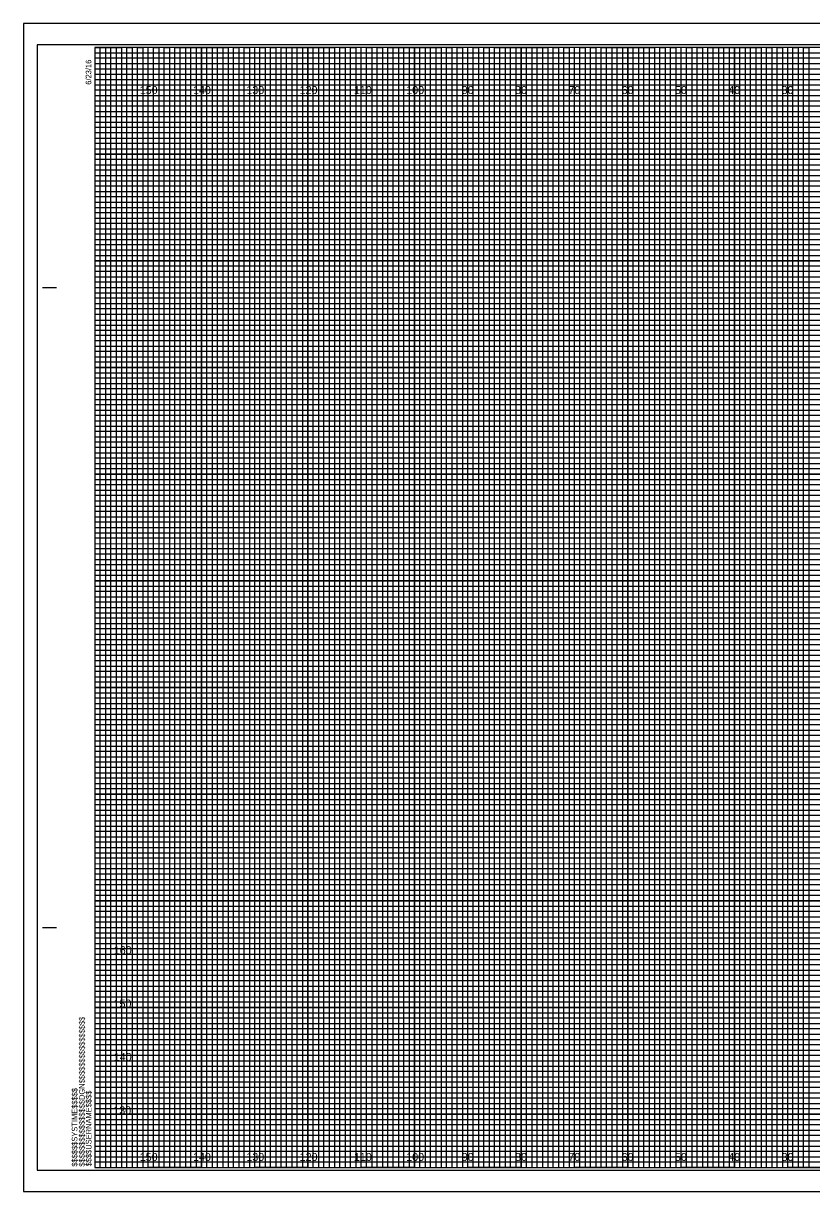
# Model space of a CAD drawing. Extents: x -13 to 323, y -5 to 874.
# Drawn here: x -13.4 to 134.5, y 655.5 to 874.5 of the extents above; entities that cross this region are included whole.
import ezdxf

# ---------------------------------------------------------------- set-up
doc = ezdxf.new("R2010")
doc.units = 0
for name, color, linetype in [('Exist Cross Section Cell', 7, 'Continuous'), ('Exist XS Center Line Elevation Label', 7, 'Continuous'), ('Exist XS Ground Line', 7, 'Continuous'), ('Prop CMT Pvmt Course 1', 7, 'Continuous'), ('Prop CMT Pvmt Course 3', 7, 'Continuous'), ('Prop CMT Pvmt Surface', 7, 'Continuous'), ('Prop CMT Pvmt Surface Shoulder', 7, 'Continuous'), ('Prop CMT Shld Paved Course 1', 7, 'Continuous'), ('Prop CMT Shld Paved Course 2', 7, 'Continuous'), ('Prop CMT Shld Paved Course 3', 7, 'Continuous'), ('Prop CMT Subgrade Earthwork', 7, 'Continuous')]:
    doc.layers.add(name, color=color, linetype=linetype)

msp = doc.modelspace()

# ---------------------------------------------------------------- linework, layer by layer
at = {"layer": 'Exist XS Center Line Elevation Label'}
for points in [[(0, 870), (5, 870), (5, 660), (15, 660), (15, 870), (25, 870), (25, 660), (35, 660), (35, 870), (45, 870), (45, 660), (55, 660), (55, 870), (65, 870), (65, 660), (75, 660), (75, 870), (85, 870), (85, 660), (95, 660), (95, 870), (105, 870), (105, 660), (115, 660), (115, 870), (125, 870), (125, 660), (135, 660)], [(0, 865), (275, 865)], [(0, 845), (320, 845), (320, 855), (0, 855)], [(0, 825), (320, 825), (320, 835), (0, 835)], [(0, 805), (320, 805), (320, 815), (0, 815)], [(0, 785), (320, 785), (320, 795), (0, 795)], [(0, 765), (320, 765), (320, 775), (0, 775)], [(0, 745), (320, 745), (320, 755), (0, 755)], [(0, 725), (320, 725), (320, 735), (0, 735)], [(0, 705), (320, 705), (320, 715), (0, 715)], [(0, 685), (320, 685), (320, 695), (0, 695)], [(0, 665), (320, 665), (320, 675), (0, 675)]]:
    msp.add_lwpolyline(points, dxfattribs=at)
at = {"layer": 'Exist XS Ground Line'}
for p, q in [((10, 870), (0, 870)), ((10, 660), (10, 870)), ((30, 870), (20, 870)), ((20, 870), (20, 660)), ((30, 660), (30, 870)), ((50, 870), (40, 870)), ((40, 870), (40, 660)), ((50, 660), (50, 870)), ((70, 870), (60, 870)), ((60, 870), (60, 660)), ((70, 660), (70, 870)), ((90, 870), (80, 870)), ((80, 870), (80, 660)), ((90, 660), (90, 870)), ((110, 870), (100, 870)), ((100, 870), (100, 660)), ((110, 660), (110, 870)), ((130, 870), (120, 870)), ((120, 870), (120, 660)), ((130, 660), (130, 870)), ((20, 660), (10, 660)), ((40, 660), (30, 660)), ((60, 660), (50, 660)), ((80, 660), (70, 660)), ((100, 660), (90, 660)), ((120, 660), (110, 660)), ((140, 660), (130, 660))]:
    msp.add_line(p, q, dxfattribs=at)
for points in [[(0, 860), (320, 860), (320, 850), (0, 850)], [(0, 840), (320, 840), (320, 830), (0, 830)], [(0, 820), (320, 820), (320, 810), (0, 810)], [(0, 800), (320, 800), (320, 790), (0, 790)], [(0, 780), (320, 780), (320, 770), (0, 770)], [(0, 760), (320, 760), (320, 750), (0, 750)], [(0, 740), (320, 740), (320, 730), (0, 730)], [(0, 720), (320, 720), (320, 710), (0, 710)], [(0, 700), (320, 700), (320, 690), (0, 690)], [(0, 680), (320, 680), (320, 670), (0, 670)]]:
    msp.add_lwpolyline(points, dxfattribs=at)
at = {"layer": 'Prop CMT Pvmt Course 3'}
msp.add_lwpolyline([(-13.4, 655.5), (323.3, 655.5), (323.3, 874.5), (-13.4, 874.5)], close=True, dxfattribs=at)
at = {"layer": 'Prop CMT Pvmt Surface'}
for p, q in [((10, 660), (10, 870)), ((20, 660), (20, 870)), ((30, 660), (30, 870)), ((40, 660), (40, 870)), ((50, 660), (50, 870)), ((60, 660), (60, 870)), ((70, 660), (70, 870)), ((80, 660), (80, 870)), ((90, 660), (90, 870)), ((100, 660), (100, 870)), ((110, 660), (110, 870)), ((120, 660), (120, 870)), ((130, 660), (130, 870)), ((0, 860), (320, 860)), ((0, 850), (320, 850)), ((0, 840), (320, 840)), ((0, 830), (320, 830)), ((0, 820), (320, 820)), ((0, 810), (320, 810)), ((0, 800), (320, 800)), ((0, 790), (320, 790)), ((0, 780), (320, 780)), ((0, 770), (320, 770)), ((0, 760), (320, 760)), ((0, 750), (320, 750)), ((0, 740), (320, 740)), ((0, 730), (320, 730)), ((0, 720), (320, 720)), ((0, 710), (320, 710)), ((0, 700), (320, 700)), ((0, 690), (320, 690)), ((0, 680), (320, 680)), ((0, 670), (320, 670))]:
    msp.add_line(p, q, dxfattribs=at)
at = {"layer": 'Prop CMT Pvmt Surface Shoulder'}
for p, q in [((323.3, 874.5), (-13.4, 874.5)), ((-13.4, 874.5), (-13.4, 655.5)), ((-13.4, 655.5), (323.3, 655.5))]:
    msp.add_line(p, q, dxfattribs=at)
at = {"layer": 'Prop CMT Shld Paved Course 1'}
for p, q in [((0, 869), (260, 869)), ((260, 867.98), (0, 867.98)), ((0, 867.98), (0, 867)), ((0, 867), (260, 867)), ((260, 865.89), (0, 865.89)), ((0, 865.89), (0, 864)), ((0, 864), (320, 864))]:
    msp.add_line(p, q, dxfattribs=at)
for points in [[(0, 863), (270, 863), (320, 863), (320, 862), (0, 862)], [(0, 861), (320, 861), (320, 859), (0, 859)], [(0, 858), (320, 858), (320, 857), (0, 856.98)], [(0, 856), (320, 856), (320, 854), (0, 854)], [(0, 853), (320, 853), (320, 852), (0, 852)], [(0, 851), (320, 851), (320, 849), (0, 849)], [(0, 848), (320, 848), (320, 847), (0, 847)], [(0, 846), (320, 846), (320, 844), (0, 844)], [(0, 843), (320, 843), (320, 842), (0, 842)], [(0, 841), (320, 841), (320, 839), (0, 839)], [(0, 838), (320, 838), (320, 837), (0, 837)], [(0, 836), (320, 836), (320, 833.95), (320, 833), (320, 832), (0, 832)], [(0, 834), (320, 834), (320, 833), (0, 833)], [(0, 831), (320, 831), (320, 829), (0, 829.03)], [(0, 829.03), (320, 829), (320, 828), (0, 828)], [(0, 827), (320, 827), (320, 826), (0, 826)], [(0, 824), (320, 824), (320, 823), (0, 823)], [(0, 822), (320, 822), (320, 821), (0, 821)], [(-0.07, 818.89), (320, 818.89), (320, 817.88), (-0.07, 817.88)], [(0, 817), (320, 817), (320, 816), (0, 816)], [(0, 814), (320, 814), (320, 813), (0, 813)], [(0, 812), (320, 812), (320, 811), (0, 811)], [(0, 809), (320, 809), (320, 808), (0, 808)], [(0, 807), (320, 807), (320, 806), (0, 806)], [(0, 804), (320, 804), (320, 803), (0, 803)], [(0, 802), (320, 802), (320, 801), (0, 801)], [(0, 799), (320, 799), (319.99, 797.98), (0, 798)], [(0, 797), (320, 797), (320, 796), (0, 796)], [(0, 794), (320, 794), (320, 793), (0, 793)], [(0, 792), (320, 792), (320, 791), (0, 791)], [(0, 789), (320, 789), (320, 788), (0, 788)], [(0, 787), (320, 787), (320, 786), (0, 786)], [(0, 784), (320, 784), (320, 783), (0, 783)], [(0, 782), (320, 782), (320, 781), (0, 781)], [(0, 779), (320, 779), (320, 778), (0, 778)], [(0, 776.99), (320.07, 776.91), (320, 776), (0, 776)], [(0, 774), (320, 774), (320, 773), (0, 773)], [(0, 772), (320, 772), (320, 771), (0, 771)], [(0, 769), (320, 769), (320, 768), (0, 768)], [(0, 767), (320, 767), (320, 766), (0, 766)], [(0, 764), (320, 764), (320, 763), (0, 763)], [(0, 762), (320, 762), (320, 761), (0, 761)], [(0, 759), (320, 759), (320, 758), (0, 758)], [(0, 757), (320, 757), (320, 756), (0, 756)], [(0, 754), (320, 754), (320, 753), (0, 753)], [(0, 752), (320, 752), (320, 751), (0, 751)], [(0, 749), (320, 749), (320, 748), (0, 748)], [(0, 747), (320, 747), (320, 746), (0, 746)], [(0, 744), (320, 744), (320, 743), (0, 743)], [(0, 742), (320, 742), (320, 741), (0, 741)], [(0, 739), (320, 739), (319.99, 737.98), (0, 738)], [(0, 737), (320, 737), (320, 736), (0, 736)], [(0, 734), (320, 734), (320, 733), (0, 733)], [(0, 732), (320, 732), (320, 731), (0, 731)], [(0, 729), (320, 729), (320, 728), (0, 728)], [(0, 727), (320, 727), (320, 726), (0, 726)], [(0, 724), (320, 724), (320, 723), (0, 723)], [(0, 722), (320, 722), (320, 721), (0, 721)], [(0, 719), (320, 719), (320, 718), (0, 718)], [(0, 716.99), (320.07, 716.91), (320, 716), (0, 716)], [(0, 714), (320, 714), (320, 713), (0, 713)], [(0, 712), (320, 712), (320, 711), (0, 711)], [(0, 709), (320, 709), (320, 708), (0, 708)], [(0, 707), (320, 707), (320, 706), (0, 706)], [(0, 704), (320, 704), (320, 703), (0, 703)], [(0, 702), (320, 702), (320, 701), (0, 701)], [(0, 699), (320, 699), (320, 698), (0, 698)], [(0, 697), (320, 697), (320, 696), (0, 696)], [(0, 694), (320, 694), (320, 693), (0, 693)], [(0, 692), (320, 692), (320, 691), (0, 691)], [(0, 689), (320, 689), (320, 688), (0, 688)], [(0, 687), (320, 687), (320, 686), (0, 686)], [(0, 684), (320, 684), (320, 683), (0, 683)], [(0, 682), (320, 682), (320, 681), (0, 681)], [(0, 679), (320, 679), (320, 678), (0, 678)], [(0, 677), (320, 677), (320, 676), (0, 676)], [(0, 674), (320, 674), (320, 673), (0, 673)], [(0, 672), (320, 672), (320, 671), (0, 671)], [(0, 669), (320, 669), (320, 668), (0, 668)], [(0, 667), (320, 667), (320, 666), (0, 666)], [(0, 664), (320, 664), (320, 663), (0, 663)], [(0, 662), (320, 662), (320, 661), (0, 661)]]:
    msp.add_lwpolyline(points, dxfattribs=at)
at = {"layer": 'Prop CMT Shld Paved Course 2'}
for p, q in [((-9.8, 825), (-7.3, 825)), ((-9.7, 825), (-7.2, 825)), ((-9.8, 705), (-7.3, 705)), ((-9.7, 705), (-7.2, 705)), ((0, 660), (0, 660)), ((0, 660), (0, 660)), ((0, 660), (0, 660)), ((0, 660), (0, 660)), ((0, 660), (0, 660)), ((0, 660), (0, 660)), ((0, 660), (0, 660))]:
    msp.add_line(p, q, dxfattribs=at)
msp.add_lwpolyline([(320, 870), (0, 870), (0, 660), (320, 660)], close=True, dxfattribs=at)
at = {"layer": 'Prop CMT Shld Paved Course 3'}
for points in [[(0, 660), (1, 660), (1, 870), (2, 870), (2, 660)], [(2, 660), (3, 660), (3, 870), (4, 870), (4, 660)], [(5, 660), (6, 660), (6, 870), (7, 870), (7, 660)], [(7, 660), (8, 660), (8, 870), (9, 870), (9, 660)], [(10, 660), (11, 660), (11, 870), (12, 870), (12, 660)], [(12, 660), (13, 660), (13, 870), (14, 870), (14, 660)], [(15, 660), (16, 660), (16, 870), (17, 870), (17, 660)], [(17, 660), (18, 660), (18, 870), (19, 870), (19, 660)], [(20, 660), (21, 660), (21, 870), (22, 870), (22, 660)], [(22, 660), (23, 660), (23, 870), (24, 870), (24, 660)], [(25, 660), (26, 660), (26, 870), (27, 870), (27, 660)], [(27, 660), (28, 660), (28, 870), (29, 870), (29, 660)], [(30, 660), (31, 660), (31, 870), (32, 870), (32, 660)], [(32, 660), (33, 660), (33, 870), (34, 870), (34, 660)], [(35, 660), (36, 660), (36, 870), (37, 870), (37, 660)], [(37, 660), (38, 660), (38, 870), (39, 870), (39, 660)], [(40, 660), (41, 660), (41, 870), (42, 870), (42, 660)], [(42, 660), (43, 660), (43, 870), (44, 870), (44, 660)], [(45, 660), (46, 660), (46, 870), (47, 870), (47, 660)], [(47, 660), (48, 660), (48, 870), (49, 870), (49, 660)], [(50, 660), (51, 660), (51, 870), (52, 870), (52, 660)], [(52, 660), (53, 660), (53, 870), (54, 870), (54, 660)], [(55, 660), (56, 660), (56, 870), (57, 870), (57, 660)], [(57, 660), (58, 660), (58, 870), (59, 870), (59, 660)], [(60, 660), (61, 660), (61, 870), (62, 870), (62, 660)], [(62, 660), (63, 660), (63, 870), (64, 870), (64, 660)], [(65, 660), (66, 660), (66, 870), (67, 870), (67, 660)], [(67, 660), (68, 660), (68, 870), (69, 870), (69, 660)], [(70, 660), (71, 660), (71, 870), (72, 870), (72, 660)], [(72, 660), (73, 660), (73, 870), (74, 870), (74, 660)], [(75, 660), (76, 660), (76, 870), (77, 870), (77, 660)], [(77, 660), (78, 660), (78, 870), (79, 870), (79, 660)], [(80, 660), (81, 660), (81, 870), (82, 870), (82, 660)], [(82, 660), (83, 660), (83, 870), (84, 870), (84, 660)], [(85, 660), (86, 660), (86, 870), (87, 870), (87, 660)], [(87, 660), (88, 660), (88, 870), (89, 870), (89, 660)], [(90, 660), (91, 660), (91, 870), (92, 870), (92, 660)], [(92, 660), (93, 660), (93, 870), (94, 870), (94, 660)], [(95, 660), (96, 660), (96, 870), (97, 870), (97, 660)], [(97, 660), (98, 660), (98, 870), (99, 870), (99, 660)], [(100, 660), (101, 660), (101, 870), (102, 870), (102, 660)], [(102, 660), (103, 660), (103, 870), (104, 870), (104, 660)], [(105, 660), (106, 660), (106, 870), (107, 870), (107, 660)], [(107, 660), (108, 660), (108, 870), (109, 870), (109, 660)], [(110, 660), (111, 660), (111, 870), (112, 870), (112, 660)], [(112, 660), (113, 660), (113, 870), (114, 870), (114, 660)], [(115, 660), (116, 660), (116, 870), (117, 870), (117, 660)], [(117, 660), (118, 660), (118, 870), (119, 870), (119, 660)], [(120, 660), (121, 660), (121, 870), (122, 870), (122, 660)], [(122, 660), (123, 660), (123, 870), (124, 870), (124, 660)], [(125, 660), (126, 660), (126, 870), (127, 870), (127, 660)], [(127, 660), (128, 660), (128, 870), (129, 870), (129, 660)], [(130, 660), (131, 660), (131, 870), (132, 870), (132, 660)], [(132, 660), (133, 660), (133, 870), (134, 870), (134, 660)]]:
    msp.add_lwpolyline(points, dxfattribs=at)
at = {"layer": 'Prop CMT Subgrade Earthwork'}
msp.add_lwpolyline([(-10.8, 659.5), (322.4, 659.5), (322.4, 870.5), (-10.8, 870.5)], close=True, dxfattribs=at)

# ---------------------------------------------------------------- texts
at = {"layer": 'Exist Cross Section Cell'}
for s, p in [('150', (8.44, 861.25)), ('140', (18.44, 861.25)), ('130', (28.44, 861.25)), ('120', (38.44, 861.25)), ('110', (48.62, 861.25)), ('100', (58.44, 861.25)), ('90', (68.86, 861.25)), ('80', (78.86, 861.25)), ('70', (88.86, 861.25)), ('60', (98.86, 861.25)), ('50', (108.86, 861.25)), ('40', (118.86, 861.25)), ('30', (128.86, 861.25)), ('150', (8.44, 661.25)), ('140', (18.44, 661.25)), ('130', (28.44, 661.25)), ('120', (38.44, 661.25)), ('110', (48.62, 661.25)), ('100', (58.44, 661.25)), ('90', (68.86, 661.25)), ('80', (78.86, 661.25)), ('70', (88.86, 661.25)), ('60', (98.86, 661.25)), ('50', (108.86, 661.25)), ('40', (118.86, 661.25)), ('30', (128.86, 661.25))]:
    msp.add_text(s, height=1.5, dxfattribs=at).set_placement(p)
at = {"layer": 'Prop CMT Pvmt Course 1'}
for s, p in [('160', (3.57, 700)), ('150', (3.52, 690)), ('140', (3.57, 680)), ('130', (3.49, 670))]:
    msp.add_text(s, height=1.5, dxfattribs=at).set_placement(p)
at = {"layer": 'Prop CMT Shld Paved Course 2'}
for s, p in [('6/23/16', (-0.65, 863)), ('$$$$$$$$$$$$$$$$DGN$$$$$$$$$$$$$$$$', (-1.88, 660.18)), ('$$$$$$SYSTIME$$$$$', (-3.26, 660.18)), ('$$$$USERNAME$$$$', (-0.62, 660.23))]:
    msp.add_text(s, height=1.05, rotation=90, dxfattribs=at).set_placement(p)

doc.saveas('drawing.dxf')
